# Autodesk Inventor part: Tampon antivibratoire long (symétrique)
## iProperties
Shininess: 64.0
Length Units: 11269
Angle Units: 11279
Time Units: 11290
Mass Units: 11283
Length Display Precision: 3
Angle Display Precision: 2
Compacted: True
Part Number: Tampon antivibratoire long (symétrique)
Document SubType Name: Modeling
Created: 2005-01
Material: Par défaut
Designer: lolo (Laurent Moretti)
Density: 0.0
Volumn: 0.0
Area: 0.0
PropertySet Name: Model Information
Control State: 0
Master: False
Checked Out: False
Author: lolo (Laurent Moretti)
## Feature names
1. Base1
